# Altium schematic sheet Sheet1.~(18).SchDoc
size A3
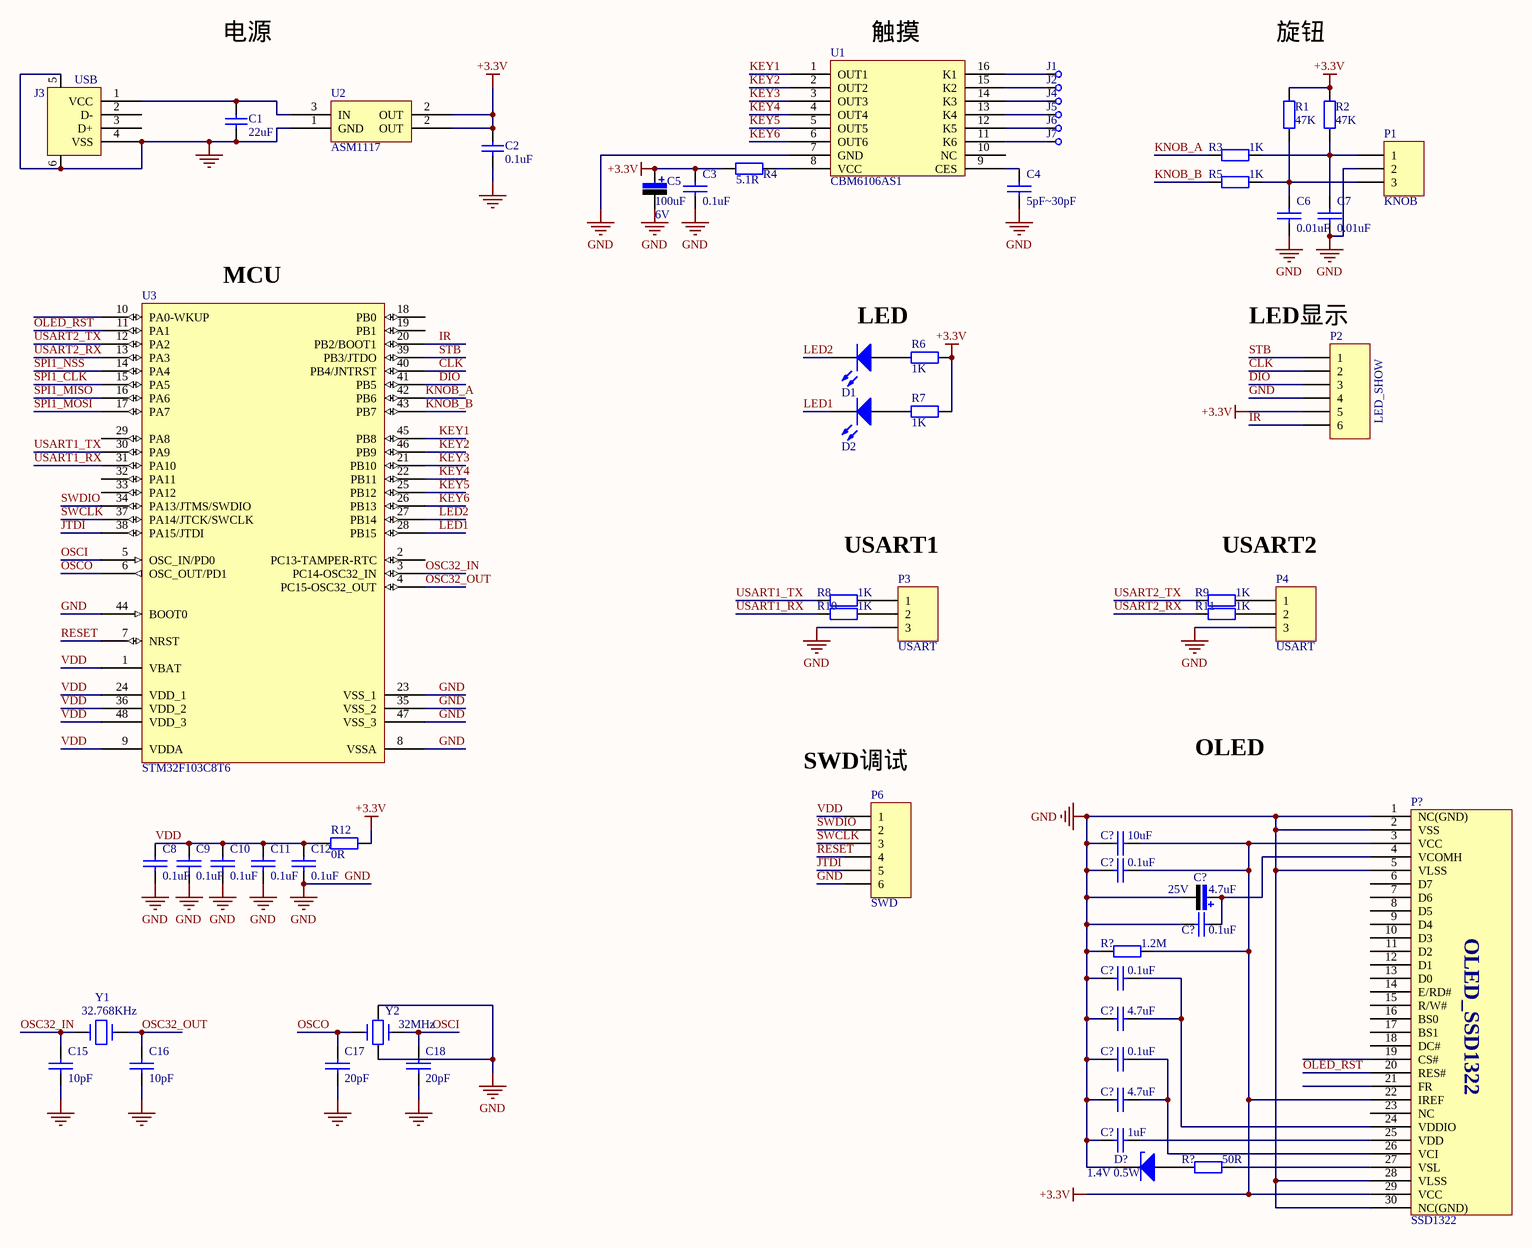
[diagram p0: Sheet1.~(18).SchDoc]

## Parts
(Parts that share a designator on the sheet are numbered #1, #2 ... from top to bottom, then left to right.)
C1  value 22uF  [0402C]  (hidden comment: Cap)
C2  value 0.1uF  [0402C]  (hidden comment: Cap)
C3  0.1uF  [0402C]
C4  5pF~30pF  [0402C]
C5  value 100uF  Vol: 6V  [CAP-3528]  (hidden comment: Cap Pol)
C6  0.01uF  [0402C]
C7  0.01uF  [0402C]
C8  0.1uF  [0402C]
C9  0.1uF  [0402C]
C10  0.1uF  [0402C]
C11  0.1uF  [0402C]
C12  0.1uF  [0402C]
C15  10pF  [0402C]
C16  10pF  [0402C]
C17  20pF  [0402C]
C18  20pF  [0402C]
C?#1  10uF  [0402C]
C?#2  0.1uF  [0402C]
C?#3  value 4.7uF  Vol: 25V  [CAP-3528]  (hidden comment: Cap Pol)
C?#4  0.1uF  [0402C]
C?#5  0.1uF  [0402C]
C?#6  4.7uF  [0402C]
C?#7  0.1uF  [0402C]
C?#8  4.7uF  [0402C]
C?#9  1uF  [0402C]
D1  LED0  [led0603]  (value not drawn)
D2  LED0  [led0603]  (value not drawn)
D?  value 1.4V 0.5W  [DIODE-1206]  (hidden comment: Diode-Z)
J1  CHECK  [CHECK-A]  (value not drawn)
J2  CHECK  [CHECK-A]  (value not drawn)
J3  USB  [USB_A1]
J4  CHECK  [CHECK-A]  (value not drawn)
J5  CHECK  [CHECK-A]  (value not drawn)
J6  CHECK  [CHECK-A]  (value not drawn)
J7  CHECK  [CHECK-A]  (value not drawn)
P1  KNOB  [HDR3X1_A]
P2  LED_SHOW  [HDR6X1_B2]
P3  USART  [HDR3X1_A]
P4  USART  [HDR3X1_A]
P6  SWD  [HDR6X1_B2]
P?  SSD1322
R1  value 47K  [0603-1]  (hidden comment: Res1)
R2  value 47K  [0603-1]  (hidden comment: Res1)
R3  value 1K  [0603-1]  (hidden comment: Res1)
R4  value 5.1R  [0603-1]  (hidden comment: Res1)
R5  value 1K  [0603-1]  (hidden comment: Res1)
R6  value 1K  [0402R]  (hidden comment: Res1)
R7  value 1K  [0402R]  (hidden comment: Res1)
R8  value 1K  [0402R]  (hidden comment: Res1)
R9  value 1K  [0402R]  (hidden comment: Res1)
R10  value 1K  [0402R]  (hidden comment: Res1)
R11  value 1K  [0402R]  (hidden comment: Res1)
R12  value 0R  [0402R]  (hidden comment: Res1)
R?#1  value 1.2M  [0402R]  (hidden comment: Res1)
R?#2  value 50R  [0402R]  (hidden comment: Res1)
U1  CBM6106AS1
U2  ASM1117  [SOT-223-3]
U3  STM32F103C8T6  [LQFP48_N]
Y1  32.768KHz  [SMD3215]
Y2  32MHz  [Y3225]

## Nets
+3.3V: C2.2 C3.1 C5.1 C?#1.1 C?#2.1 P2.5 P?.3(VCC) P?.22(IREF) P?.29(VCC) R1.2 R2.2 R4.1 R6.1 R7.1 R12.2 R?#1.1 U2.2(OUT)
GND: C1.1 C2.1 C3.2 C4.2 C5.2 C6.2 C7.2 C8.2 C9.2 C10.2 C11.2 C12.2 C15.2 C16.2 C17.2 C18.2 C?#1.2 C?#2.2 C?#3.2 C?#4.2 C?#5.2 C?#6.2 C?#7.2 C?#8.2 C?#9.2 D?.2(K) J3.4(VSS) J3.5 J3.6 P1.2 P2.4 P3.3 P4.3 P6.6 P?.1(NC(GND)) P?.2(VSS) P?.5(VLSS) P?.28(VLSS) P?.30(NC(GND)) R?#1.2 U1.7(GND) U2.1(GND) U3.8(VSSA) U3.23(VSS_1) U3.35(VSS_2) U3.44(BOOT0) U3.47(VSS_3) Y2.2 Y2.4
CLK: P2.2 U3.40(PB4/JNTRST)
DIO: P2.3 U3.41(PB5)
IR: P2.6 U3.20(PB2/BOOT1)
JTDI: P6.5 U3.38(PA15/JTDI)
KEY1: U1.1(OUT1) U3.45(PB8)
KEY2: U1.2(OUT2) U3.46(PB9)
KEY3: U1.3(OUT3) U3.21(PB10)
KEY4: U1.4(OUT4) U3.22(PB11)
KEY5: U1.5(OUT5) U3.25(PB12)
KEY6: U1.6(OUT6) U3.26(PB13)
KNOB_A: R3.1 U3.42(PB6)
KNOB_B: R5.1 U3.43(PB7)
LED1: D2.2(K) U3.28(PB15)
LED2: D1.2(K) U3.27(PB14)
OLED_RST: P?.20(RES#) U3.11(PA1)
OSC32_IN: C15.1 U3.3(PC14-OSC32_IN) Y1.1
OSC32_OUT: C16.1 U3.4(PC15-OSC32_OUT) Y1.2
OSCI: C18.1 U3.5(OSC_IN/PD0) Y2.3
OSCO: C17.1 U3.6(OSC_OUT/PD1) Y2.1
RESET: P6.4 U3.7(NRST)
SPI1_CLK: U3.15(PA5)
SPI1_MISO: U3.16(PA6)
SPI1_MOSI: U3.17(PA7)
SPI1_NSS: U3.14(PA4)
STB: P2.1 U3.39(PB3/JTDO)
SWCLK: P6.3 U3.37(PA14/JTCK/SWCLK)
SWDIO: P6.2 U3.34(PA13/JTMS/SWDIO)
USART1_RX: R10.2 U3.31(PA10)
USART1_TX: R8.2 U3.30(PA9)
USART2_RX: R11.2 U3.13(PA3)
USART2_TX: R9.2 U3.12(PA2)
VDD: C8.1 C9.1 C10.1 C11.1 C12.1 P6.1 R12.1 U3.1(VBAT) U3.9(VDDA) U3.24(VDD_1) U3.36(VDD_2) U3.48(VDD_3)
NetC1_2: C1.2 J3.1(VCC) U2.3(IN)
NetC4_1: C4.1 U1.9(CES)
NetC6_1: C6.1 P1.3 R1.1 R5.2
NetC7_1: C7.1 P1.1 R2.1 R3.2
NetC?#3_1: C?#3.1 C?#4.1 P?.4(VCOMH)
NetC?#5_1: C?#5.1 C?#6.1 P?.24(VDDIO)
NetC?#7_1: C?#7.1 C?#8.1 P?.26(VCI)
NetC?#9_1: C?#9.1 P?.25(VDD)
NetD1_1: D1.1(A) R6.2
NetD2_1: D2.1(A) R7.2
NetD?_1: D?.1(A) R?#2.2
NetJ1_1: J1.1 U1.16(K1)
NetJ2_1: J2.1 U1.15(K2)
NetJ4_1: J4.1 U1.14(K3)
NetJ5_1: J5.1 U1.13(K4)
NetJ6_1: J6.1 U1.12(K5)
NetJ7_1: J7.1 U1.11(K6)
NetP3_1: P3.1 R8.1
NetP3_2: P3.2 R10.1
NetP4_1: P4.1 R9.1
NetP4_2: P4.2 R11.1
NetP?_27: P?.27(VSL) R?#2.1
NetR4_2: R4.2 U1.8(VCC)

Not connected (* = marked no-connect by the designer): J3 2(D-) 3(D+); P? 6(D7) 7(D6) 8(D5) 9(D4) 10(D3) 11(D2) 12(D1) 13(D0) 14(E/RD#) 15(R/W#) 16(BS0) 17(BS1) 18(DC#) 19(CS#) 21(FR) 23(NC); U1 10(NC); U3 2(PC13-TAMPER-RTC) 10(PA0-WKUP) 18(PB0) 19(PB1) 29(PA8) 32(PA11) 33(PA12)

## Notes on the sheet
- 电源
- (near U1) 触摸
- 旋钮
- (near U3) MCU
- LED
- (near P2) LED显示
- USART1
- USART2
- (near P6) SWD调试
- OLED

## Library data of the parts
C1 C2 = Cap: 无极性电容
C3 C4 C6-C12 C15-C18 C?#1 C?#2 C?#4-C?#9 = CAP: Capacitor
C5 C?#3 = Cap Pol: 极性电解电容
D1 D2 = LED0: 发光二极管
D? = Diode-Z: 稳压二极管
J1 J2 J4-J7 = CHECK: 测试点
J3 = USB: USB接口
P1 P3 P4 = Header 3: 接插件
P2 P6 = Header 6: 接插件
R1-R12 R?#1 R?#2 = Res1: 贴片电阻
U2 = ASM1117: 3.3V稳压芯片
U3 = STM32F103C8T6: STM32 ARM-based 32-bit MCU with 64 Kbytes Flash, 48-pin LQFP, Industrial Temperature
Y1 = CRYSTAL
Y2 = CRYSTAL1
